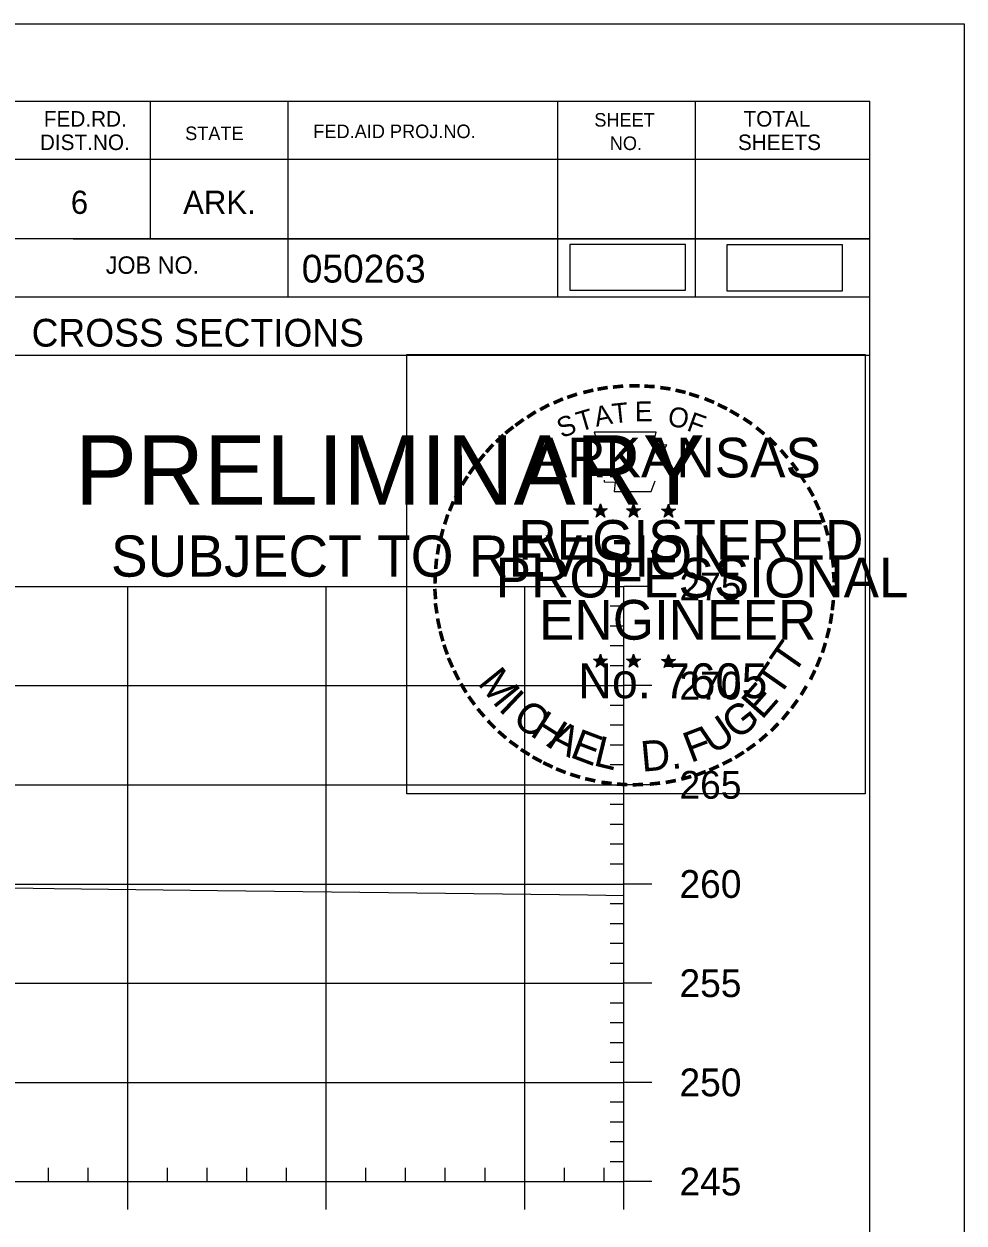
# Model space of a CAD drawing. Extents: x 1365647 to 1367999, y 387113 to 400173.
# Drawn here: x 1366009.7 to 1366057, y 388165.6 to 388226.1 of the extents above; entities that cross this region are included whole.
import ezdxf

# ---------------------------------------------------------------- set-up
doc = ezdxf.new("R2010")
doc.units = 0
for name, color, linetype in [('R_Axis', 7, 'Continuous'), ('R_Axis Annot', 7, 'Continuous'), ('R_Border', 7, 'Continuous'), ('R_Border PE', 7, 'Continuous'), ('R_Border Prem', 7, 'Continuous'), ('R_Detour', 7, 'Continuous'), ('R_Exist Surface', 7, 'Continuous'), ('R_Grid', 7, 'Continuous'), ('R_No Plot', 7, 'Continuous')]:
    doc.layers.add(name, color=color, linetype=linetype)

msp = doc.modelspace()

# ---------------------------------------------------------------- linework, layer by layer
at = {"layer": 'R_Axis'}
for p, q in [((1366039.888, 388167.731), (1366039.888, 388197.731)), ((1366041.288, 388197.731), (1366039.888, 388197.731)), ((1366039.888, 388196.731), (1366039.188, 388196.731)), ((1366039.888, 388195.731), (1366039.188, 388195.731)), ((1366039.888, 388194.731), (1366039.188, 388194.731)), ((1366039.888, 388193.731), (1366039.188, 388193.731)), ((1366041.288, 388192.731), (1366039.888, 388192.731)), ((1366039.888, 388191.731), (1366039.188, 388191.731)), ((1366039.888, 388190.731), (1366039.188, 388190.731)), ((1366039.888, 388189.731), (1366039.188, 388189.731)), ((1366039.888, 388188.731), (1366039.188, 388188.731)), ((1366041.288, 388187.731), (1366039.888, 388187.731)), ((1366039.888, 388186.731), (1366039.188, 388186.731)), ((1366039.888, 388185.731), (1366039.188, 388185.731)), ((1366039.888, 388184.731), (1366039.188, 388184.731)), ((1366039.888, 388183.731), (1366039.188, 388183.731)), ((1366041.288, 388182.731), (1366039.888, 388182.731)), ((1366039.888, 388181.731), (1366039.188, 388181.731)), ((1366039.888, 388180.731), (1366039.188, 388180.731)), ((1366039.888, 388179.731), (1366039.188, 388179.731)), ((1366039.888, 388178.731), (1366039.188, 388178.731)), ((1366041.288, 388177.731), (1366039.888, 388177.731)), ((1366039.888, 388176.731), (1366039.188, 388176.731)), ((1366039.888, 388175.731), (1366039.188, 388175.731)), ((1366039.888, 388174.731), (1366039.188, 388174.731)), ((1366039.888, 388173.731), (1366039.188, 388173.731)), ((1366041.288, 388172.731), (1366039.888, 388172.731)), ((1366039.888, 388171.731), (1366039.188, 388171.731)), ((1366039.888, 388170.731), (1366039.188, 388170.731)), ((1366039.888, 388169.731), (1366039.188, 388169.731)), ((1366039.888, 388168.731), (1366039.188, 388168.731)), ((1366010.888, 388167.731), (1366010.888, 388168.431)), ((1366012.888, 388167.731), (1366012.888, 388168.431)), ((1366016.888, 388167.731), (1366016.888, 388168.431)), ((1366018.888, 388167.731), (1366018.888, 388168.431)), ((1366020.888, 388167.731), (1366020.888, 388168.431)), ((1366022.888, 388167.731), (1366022.888, 388168.431)), ((1366026.888, 388167.731), (1366026.888, 388168.431)), ((1366028.888, 388167.731), (1366028.888, 388168.431)), ((1366030.888, 388167.731), (1366030.888, 388168.431)), ((1366032.888, 388167.731), (1366032.888, 388168.431)), ((1366036.888, 388167.731), (1366036.888, 388168.431)), ((1366038.888, 388167.731), (1366038.888, 388168.431)), ((1365749.888, 388167.731), (1366039.888, 388167.731)), ((1366014.888, 388166.331), (1366014.888, 388167.731)), ((1366024.888, 388166.331), (1366024.888, 388167.731)), ((1366034.888, 388166.331), (1366034.888, 388167.731)), ((1366039.888, 388166.331), (1366039.888, 388167.731)), ((1366041.288, 388167.731), (1366039.888, 388167.731))]:
    msp.add_line(p, q, dxfattribs=at)
at = {"layer": 'R_Border'}
for p, q in [((1365736.095, 388222.191), (1366052.275, 388222.191)), ((1366016.015, 388222.191), (1366016.015, 388215.251)), ((1366022.955, 388222.191), (1366022.955, 388212.311)), ((1366036.535, 388222.191), (1366036.535, 388212.311)), ((1366043.475, 388222.191), (1366043.475, 388212.311)), ((1366052.275, 388016.731), (1366052.275, 388222.191)), ((1366052.275, 388219.251), (1366009.175, 388219.251)), ((1366052.275, 388219.271), (1366052.275, 388219.271)), ((1366052.275, 388215.251), (1366009.175, 388215.251)), ((1366012.135, 388215.251), (1366052.275, 388215.251)), ((1366052.275, 388212.311), (1365970.015, 388212.311)), ((1366009.175, 388209.391), (1366052.275, 388209.391))]:
    msp.add_line(p, q, dxfattribs=at)
at = {"layer": 'R_Border PE'}
for p, q in [((1366038.705, 388201.891), (1366038.664, 388201.639)), ((1366038.705, 388201.526), (1366038.705, 388201.891)), ((1366038.705, 388201.891), (1366038.754, 388201.641)), ((1366040.375, 388201.891), (1366040.334, 388201.639)), ((1366040.375, 388201.526), (1366040.375, 388201.891)), ((1366040.375, 388201.891), (1366040.424, 388201.641)), ((1366042.139, 388201.879), (1366042.098, 388201.627)), ((1366042.139, 388201.514), (1366042.139, 388201.879)), ((1366042.139, 388201.879), (1366042.188, 388201.629)), ((1366038.356, 388201.637), (1366038.705, 388201.526)), ((1366038.356, 388201.637), (1366038.609, 388201.592)), ((1366038.356, 388201.637), (1366038.593, 388201.515)), ((1366038.489, 388201.229), (1366038.705, 388201.526)), ((1366038.489, 388201.229), (1366038.615, 388201.473)), ((1366038.489, 388201.229), (1366038.703, 388201.446)), ((1366038.918, 388201.229), (1366038.703, 388201.443)), ((1366039.052, 388201.637), (1366038.705, 388201.526)), ((1366038.918, 388201.229), (1366038.705, 388201.526)), ((1366039.052, 388201.637), (1366038.766, 388201.588)), ((1366038.918, 388201.229), (1366038.781, 388201.52)), ((1366039.052, 388201.637), (1366038.848, 388201.535)), ((1366040.026, 388201.637), (1366040.375, 388201.526)), ((1366040.026, 388201.637), (1366040.279, 388201.592)), ((1366040.026, 388201.637), (1366040.263, 388201.515)), ((1366040.159, 388201.229), (1366040.375, 388201.526)), ((1366040.159, 388201.229), (1366040.285, 388201.473)), ((1366040.159, 388201.229), (1366040.373, 388201.446)), ((1366040.588, 388201.229), (1366040.373, 388201.443)), ((1366040.722, 388201.637), (1366040.375, 388201.526)), ((1366040.588, 388201.229), (1366040.375, 388201.526)), ((1366040.722, 388201.637), (1366040.436, 388201.588)), ((1366040.588, 388201.229), (1366040.451, 388201.52)), ((1366040.722, 388201.637), (1366040.518, 388201.535)), ((1366041.79, 388201.625), (1366042.139, 388201.514)), ((1366041.79, 388201.625), (1366042.043, 388201.58)), ((1366041.79, 388201.625), (1366042.027, 388201.503)), ((1366041.923, 388201.217), (1366042.139, 388201.514)), ((1366041.923, 388201.217), (1366042.049, 388201.461)), ((1366041.923, 388201.217), (1366042.137, 388201.434)), ((1366042.352, 388201.217), (1366042.137, 388201.431)), ((1366042.486, 388201.625), (1366042.139, 388201.514)), ((1366042.352, 388201.217), (1366042.139, 388201.514)), ((1366042.486, 388201.625), (1366042.2, 388201.576)), ((1366042.352, 388201.217), (1366042.215, 388201.508)), ((1366042.486, 388201.625), (1366042.282, 388201.523)), ((1366038.352, 388194.064), (1366038.701, 388193.953)), ((1366038.352, 388194.064), (1366038.605, 388194.019)), ((1366038.352, 388194.064), (1366038.589, 388193.942)), ((1366038.701, 388194.318), (1366038.66, 388194.066)), ((1366038.701, 388193.953), (1366038.701, 388194.318)), ((1366038.701, 388194.318), (1366038.75, 388194.068)), ((1366039.048, 388194.064), (1366038.701, 388193.953)), ((1366039.048, 388194.064), (1366038.762, 388194.015)), ((1366039.048, 388194.064), (1366038.844, 388193.962)), ((1366040.021, 388194.064), (1366040.37, 388193.953)), ((1366040.021, 388194.064), (1366040.274, 388194.019)), ((1366040.021, 388194.064), (1366040.258, 388193.942)), ((1366040.37, 388194.318), (1366040.329, 388194.066)), ((1366040.37, 388193.953), (1366040.37, 388194.318)), ((1366040.37, 388194.318), (1366040.419, 388194.068)), ((1366040.717, 388194.064), (1366040.37, 388193.953)), ((1366040.717, 388194.064), (1366040.431, 388194.015)), ((1366040.717, 388194.064), (1366040.513, 388193.962)), ((1366041.788, 388194.054), (1366042.137, 388193.943)), ((1366041.788, 388194.054), (1366042.041, 388194.009)), ((1366041.788, 388194.054), (1366042.025, 388193.932)), ((1366042.137, 388194.308), (1366042.096, 388194.056)), ((1366042.137, 388193.943), (1366042.137, 388194.308)), ((1366042.137, 388194.308), (1366042.186, 388194.058)), ((1366042.484, 388194.054), (1366042.137, 388193.943)), ((1366042.484, 388194.054), (1366042.198, 388194.005)), ((1366042.484, 388194.054), (1366042.28, 388193.952)), ((1366038.485, 388193.656), (1366038.701, 388193.953)), ((1366038.485, 388193.656), (1366038.611, 388193.9)), ((1366038.485, 388193.656), (1366038.699, 388193.873)), ((1366038.914, 388193.656), (1366038.699, 388193.87)), ((1366038.914, 388193.656), (1366038.701, 388193.953)), ((1366038.914, 388193.656), (1366038.777, 388193.947)), ((1366040.154, 388193.656), (1366040.37, 388193.953)), ((1366040.154, 388193.656), (1366040.28, 388193.9)), ((1366040.154, 388193.656), (1366040.368, 388193.873)), ((1366040.583, 388193.656), (1366040.368, 388193.87)), ((1366040.583, 388193.656), (1366040.37, 388193.953)), ((1366040.583, 388193.656), (1366040.446, 388193.947)), ((1366041.921, 388193.646), (1366042.137, 388193.943)), ((1366041.921, 388193.646), (1366042.047, 388193.89)), ((1366041.921, 388193.646), (1366042.135, 388193.863)), ((1366042.35, 388193.646), (1366042.135, 388193.86)), ((1366042.35, 388193.646), (1366042.137, 388193.943)), ((1366042.35, 388193.646), (1366042.213, 388193.937))]:
    msp.add_line(p, q, dxfattribs=at)
for points in [[(1366038.397, 388205.515), (1366038.666, 388204.688)], [(1366041.908, 388204.593), (1366042.05, 388204.877), (1366041.365, 388204.853), (1366041.513, 388205.515), (1366038.397, 388205.515)], [(1366038.889, 388203.092), (1366038.889, 388203.005), (1366039.452, 388202.986), (1366039.398, 388202.513), (1366041.268, 388202.513), (1366041.469, 388203.049)], [(1366038.705, 388201.891), (1366038.918, 388201.229), (1366038.356, 388201.637), (1366039.052, 388201.637), (1366038.489, 388201.229), (1366038.705, 388201.891)], [(1366040.375, 388201.891), (1366040.588, 388201.229), (1366040.026, 388201.637), (1366040.722, 388201.637), (1366040.159, 388201.229), (1366040.375, 388201.891)], [(1366042.139, 388201.879), (1366042.352, 388201.217), (1366041.79, 388201.625), (1366042.486, 388201.625), (1366041.923, 388201.217), (1366042.139, 388201.879)], [(1366038.701, 388194.318), (1366038.914, 388193.656), (1366038.352, 388194.064), (1366039.048, 388194.064), (1366038.485, 388193.656), (1366038.701, 388194.318)], [(1366040.37, 388194.318), (1366040.583, 388193.656), (1366040.021, 388194.064), (1366040.717, 388194.064), (1366040.154, 388193.656), (1366040.37, 388194.318)], [(1366042.137, 388194.308), (1366042.35, 388193.646), (1366041.788, 388194.054), (1366042.484, 388194.054), (1366041.921, 388193.646), (1366042.137, 388194.308)]]:
    msp.add_lwpolyline(points, dxfattribs=at)
for centre, radius in [((1366038.704, 388201.526), 0.172), ((1366038.704, 388201.526), 0.145), ((1366038.704, 388201.526), 0.116), ((1366038.704, 388201.526), 0.0991), ((1366038.704, 388201.526), 0.0747), ((1366038.704, 388201.526), 0.0495), ((1366038.704, 388201.526), 0.0296), ((1366040.374, 388201.526), 0.172), ((1366040.374, 388201.526), 0.145), ((1366040.374, 388201.526), 0.116), ((1366040.374, 388201.526), 0.0991), ((1366040.374, 388201.526), 0.0747), ((1366040.374, 388201.526), 0.0495), ((1366040.374, 388201.526), 0.0296), ((1366042.138, 388201.514), 0.172), ((1366042.138, 388201.514), 0.145), ((1366042.138, 388201.514), 0.116), ((1366042.138, 388201.514), 0.0991), ((1366042.138, 388201.514), 0.0747), ((1366042.138, 388201.514), 0.0495), ((1366042.138, 388201.514), 0.0296), ((1366038.7, 388193.953), 0.172), ((1366038.7, 388193.953), 0.145), ((1366038.7, 388193.953), 0.116), ((1366038.7, 388193.953), 0.0991), ((1366038.7, 388193.953), 0.0747), ((1366038.7, 388193.953), 0.0495), ((1366038.7, 388193.953), 0.0296), ((1366040.369, 388193.953), 0.172), ((1366040.369, 388193.953), 0.145), ((1366040.369, 388193.953), 0.116), ((1366040.369, 388193.953), 0.0991), ((1366040.369, 388193.953), 0.0747), ((1366040.369, 388193.953), 0.0495), ((1366040.369, 388193.953), 0.0296), ((1366042.136, 388193.943), 0.172), ((1366042.136, 388193.943), 0.145), ((1366042.136, 388193.943), 0.116), ((1366042.136, 388193.943), 0.0991), ((1366042.136, 388193.943), 0.0747), ((1366042.136, 388193.943), 0.0495), ((1366042.136, 388193.943), 0.0296)]:
    msp.add_circle(centre, radius, dxfattribs=at)
at = {"layer": 'R_Detour'}
for points in [[(1366037.165, 388212.662), (1366042.998, 388212.662), (1366042.998, 388214.972), (1366037.165, 388214.972)], [(1366045.079, 388212.634), (1366050.912, 388212.634), (1366050.912, 388214.944), (1366045.079, 388214.944)]]:
    msp.add_lwpolyline(points, close=True, dxfattribs=at)
at = {"layer": 'R_Exist Surface'}
msp.add_lwpolyline([(1365960.814, 388184.054), (1365971.688, 388183.636), (1365984.007, 388183.233), (1366000.536, 388182.674), (1366011.168, 388182.511), (1366019.406, 388182.405), (1366038.063, 388182.179), (1366039.888, 388182.155)], dxfattribs=at)
at = {"layer": 'R_Grid'}
for p, q in [((1365749.888, 388197.731), (1366039.888, 388197.731)), ((1366014.888, 388167.731), (1366014.888, 388197.731)), ((1366024.888, 388167.731), (1366024.888, 388197.731)), ((1366034.888, 388167.731), (1366034.888, 388197.731)), ((1366039.888, 388167.731), (1366039.888, 388197.731)), ((1365749.888, 388192.731), (1366039.888, 388192.731)), ((1365749.888, 388187.731), (1366039.888, 388187.731)), ((1365749.888, 388182.731), (1366039.888, 388182.731)), ((1365749.888, 388177.731), (1366039.888, 388177.731)), ((1365749.888, 388172.731), (1366039.888, 388172.731)), ((1365749.888, 388167.731), (1366039.888, 388167.731))]:
    msp.add_line(p, q, dxfattribs=at)
at = {"layer": 'R_No Plot'}
msp.add_line((1365723.694, 388226.085), (1366057.027, 388226.085), dxfattribs=at)
for points in [[(1365723.687, 388226.085), (1366057.027, 388226.085), (1366057.027, 388012.748), (1365723.687, 388012.748)], [(1366028.946, 388209.423), (1366052.044, 388209.423), (1366052.044, 388187.273), (1366028.946, 388187.273)]]:
    msp.add_lwpolyline(points, close=True, dxfattribs=at)

# ---------------------------------------------------------------- texts
at = {"layer": 'R_Axis Annot'}
for s, p in [('275', (1366042.688, 388197.031)), ('270', (1366042.688, 388192.031)), ('265', (1366042.688, 388187.031)), ('260', (1366042.688, 388182.031)), ('255', (1366042.688, 388177.031)), ('250', (1366042.688, 388172.031)), ('245', (1366042.688, 388167.031))]:
    msp.add_text(s, height=1.4, dxfattribs=at).set_placement(p)
at = {"layer": 'R_Border'}
for s, height, p in [('FED.RD.', 0.7819, (1366010.655, 388220.911)), ('SHEET', 0.684, (1366038.395, 388220.911)), ('TOTAL', 0.7819, (1366045.915, 388220.911)), ('STATE', 0.684, (1366017.775, 388220.231)), ('FED.AID PROJ.NO.', 0.684, (1366024.235, 388220.331)), ('DIST.NO.', 0.7819, (1366010.455, 388219.731)), ('NO.', 0.684, (1366039.175, 388219.731)), ('SHEETS', 0.7819, (1366045.635, 388219.731)), ('6', 1.172, (1366012.015, 388216.511)), ('ARK.', 1.1723, (1366017.675, 388216.511)), ('JOB NO.', 0.8792, (1366013.775, 388213.491)), ('050263', 1.4, (1366023.651, 388213.05)), ('CROSS SECTIONS', 1.4, (1366010.038, 388209.821))]:
    msp.add_text(s, height=height, rotation=360, dxfattribs=at).set_placement(p)
at = {"layer": 'R_Border PE'}
for s, height, rotation, p in [('-', 1.6, 5.89682, (1366039.302, 388207.155)), ('-', 1.6, 0.18623, (1366040.074, 388207.227)), ('-', 1.6, 357.74304, (1366040.797, 388207.214)), ('-', 1.6, 24.30721, (1366036.511, 388206.373)), ('-', 1.6, 19.17608, (1366037.145, 388206.642)), ('-', 1.6, 13.63015, (1366037.895, 388206.883)), ('-', 1.6, 10.21935, (1366038.573, 388207.045)), ('-', 1.6, 352.16172, (1366041.541, 388207.158)), ('-', 1.6, 347.20489, (1366042.26, 388207.044)), ('-', 1.6, 342.3362, (1366042.895, 388206.889)), ('-', 1.6, 337.85509, (1366043.63, 388206.666)), ('-', 1.6, 28.79182, (1366035.878, 388206.056)), ('T', 1, 16.4036, (1366037.666, 388205.524)), ('A', 1, 11.21318, (1366038.492, 388205.775)), ('T', 1, 6.02276, (1366039.341, 388205.941)), ('E', 1, 0.83234, (1366040.446, 388206.051)), ('O', 1, 350.4515, (1366042.05, 388205.841)), ('-', 1.6, 334.12109, (1366044.261, 388206.395)), ('-', 1.6, 329.64089, (1366044.84, 388206.112)), ('-', 1.6, 36.23174, (1366034.703, 388205.291)), ('-', 1.6, 34.06357, (1366035.281, 388205.686)), ('S', 1, 21.59401, (1366036.752, 388205.193)), ('F', 1, 340.07066, (1366043.004, 388205.613)), ('-', 1.6, 325.86266, (1366045.483, 388205.751)), ('-', 1.6, 38.95066, (1366034.227, 388204.913)), ('-', 1.6, 320.52971, (1366046.093, 388205.325)), ('-', 1.6, 48.42305, (1366033.346, 388204.018)), ('-', 1.6, 42.96224, (1366033.794, 388204.496)), ('ARKANSAS', 2, 360, (1366035.25, 388203.227)), ('-', 1.6, 315.57859, (1366046.692, 388204.837)), ('-', 1.6, 50.61417, (1366032.943, 388203.532)), ('-', 1.6, 309.87973, (1366047.261, 388204.287)), ('-', 1.6, 54.23247, (1366032.53, 388202.965)), ('-', 1.6, 306.65218, (1366047.786, 388203.685)), ('-', 1.6, 58.07063, (1366032.205, 388202.438)), ('-', 1.4, 303.67529, (1366048.272, 388203.117)), ('-', 1.6, 62.87135, (1366031.892, 388201.824)), ('-', 1.6, 299.66835, (1366048.591, 388202.51)), ('-', 1.6, 67.77427, (1366031.633, 388201.213)), ('-', 1.6, 294.66279, (1366048.915, 388201.898)), ('-', 1.6, 72.39447, (1366031.414, 388200.583)), ('DWB', 0.01, 360, (1366038.691, 388201.521)), ('DWB', 0.01, 360, (1366040.361, 388201.521)), ('DWB', 0.01, 360, (1366042.125, 388201.509)), ('-', 1.6, 290.57283, (1366049.172, 388201.321)), ('-', 1.6, 75.46096, (1366031.217, 388199.869)), ('REGISTERED', 2, 360, (1366034.572, 388199.078)), ('-', 1.6, 285.12326, (1366049.406, 388200.741)), ('-', 1.6, 280.54934, (1366049.606, 388199.999)), ('-', 1.6, 81.20126, (1366031.085, 388199.156)), ('-', 1.6, 85.18634, (1366031.009, 388198.465)), ('PROFESSIONAL', 2, 360, (1366033.424, 388197.174)), ('-', 1.6, 276.59616, (1366049.768, 388199.231)), ('-', 1.6, 89.06224, (1366030.984, 388197.764)), ('-', 1.6, 274.33011, (1366049.828, 388198.509)), ('-', 1.6, 94.19588, (1366031.019, 388197.039)), ('-', 1.6, 269.94067, (1366049.862, 388197.877)), ('ENGINEER', 2, 360, (1366035.611, 388195.049)), ('-', 1.6, 263.5172, (1366049.843, 388197.211)), ('-', 1.6, 98.94793, (1366031.091, 388196.372)), ('-', 1.6, 101.71495, (1366031.226, 388195.639)), ('-', 1.6, 260.99529, (1366049.772, 388196.557)), ('-', 1.6, 105.45785, (1366031.388, 388195.044)), ('-', 1.6, 255.7626, (1366049.662, 388195.879)), ('-', 1.6, 109.08742, (1366031.603, 388194.413)), ('T', 1.54, 55.05496, (1366048.42, 388193.218)), ('-', 1.6, 252.86809, (1366049.481, 388195.159)), ('-', 1.6, 114.06432, (1366031.857, 388193.817)), ('-', 1.6, 247.88866, (1366049.258, 388194.486)), ('-', 1.6, 115.72885, (1366032.162, 388193.199)), ('M', 1.54, 308.91747, (1366032.472, 388192.844)), ('No. 7605', 1.757, 360, (1366037.585, 388192.098)), ('DWB', 0.01, 360, (1366038.686, 388193.949)), ('DWB', 0.01, 360, (1366040.355, 388193.947)), ('DWB', 0.01, 360, (1366042.122, 388193.938)), ('T', 1.54, 55.05496, (1366047.689, 388192.098)), ('-', 1.6, 244.61971, (1366048.996, 388193.857)), ('-', 1.6, 120.44712, (1366032.519, 388192.613)), ('E', 1.54, 48.73133, (1366046.843, 388190.971)), ('-', 1.6, 125.89344, (1366032.922, 388192.052)), ('I', 1.54, 316.46364, (1366033.514, 388191.524)), ('-', 1.6, 239.07125, (1366048.602, 388193.105)), ('-', 1.6, 130.71812, (1366033.384, 388191.5)), ('C', 1.54, 324.01974, (1366034.187, 388190.901)), ('G', 1.54, 38.21734, (1366045.59, 388189.951)), ('-', 1.6, 233.84524, (1366048.2, 388192.452)), ('-', 1.6, 134.22381, (1366033.901, 388190.955)), ('H', 1.54, 327.53419, (1366035.097, 388190.246)), ('U', 1.54, 34.40523, (1366044.391, 388189.218)), ('-', 1.6, 231.25377, (1366047.77, 388191.886)), ('-', 1.6, 138.93382, (1366034.426, 388190.491)), ('A', 1.54, 332.55127, (1366035.951, 388189.709)), ('E', 1.54, 339.20679, (1366037.109, 388189.147)), ('F', 1.54, 20.82016, (1366043.254, 388188.824)), ('-', 1.6, 221.08509, (1366046.769, 388190.813)), ('-', 1.6, 225.76533, (1366047.291, 388191.322)), ('-', 1.6, 144.64634, (1366034.982, 388190.085)), ('L', 1.54, 346.2929, (1366038.301, 388188.723)), ('D.', 1.54, 5.26016, (1366040.804, 388188.386)), ('-', 1.6, 215.73633, (1366046.22, 388190.341)), ('-', 1.6, 148.08978, (1366035.543, 388189.714)), ('-', 1.6, 151.57039, (1366036.122, 388189.389)), ('-', 1.6, 212.24909, (1366045.686, 388189.954)), ('-', 1.6, 154.60019, (1366036.644, 388189.142)), ('-', 1.6, 158.56121, (1366037.268, 388188.888)), ('-', 1.6, 204.25161, (1366044.504, 388189.289)), ('-', 1.6, 207.35684, (1366045.128, 388189.608)), ('-', 1.6, 162.79826, (1366037.955, 388188.675)), ('-', 1.6, 167.55551, (1366038.67, 388188.511)), ('-', 1.6, 173.11546, (1366039.442, 388188.401)), ('-', 1.6, 191.28576, (1366042.479, 388188.575)), ('-', 1.6, 195.47429, (1366043.208, 388188.774)), ('-', 1.6, 200.71842, (1366043.885, 388189.016)), ('-', 1.6, 176.51827, (1366040.19, 388188.348)), ('-', 1.6, 181.59176, (1366040.934, 388188.367)), ('-', 1.6, 185.81666, (1366041.743, 388188.443))]:
    msp.add_text(s, height=height, rotation=rotation, dxfattribs=at).set_placement(p)
at = {"layer": 'R_Border Prem'}
for s, height, p in [('PRELIMINARY', 3.5, (1366012.226, 388201.854)), ('DWB', 0.01, (1366012.973, 388203.703)), ('SUBJECT TO REVISION', 2.07511, (1366014.035, 388198.225))]:
    msp.add_text(s, height=height, rotation=360, dxfattribs=at).set_placement(p)

doc.saveas('drawing.dxf')
